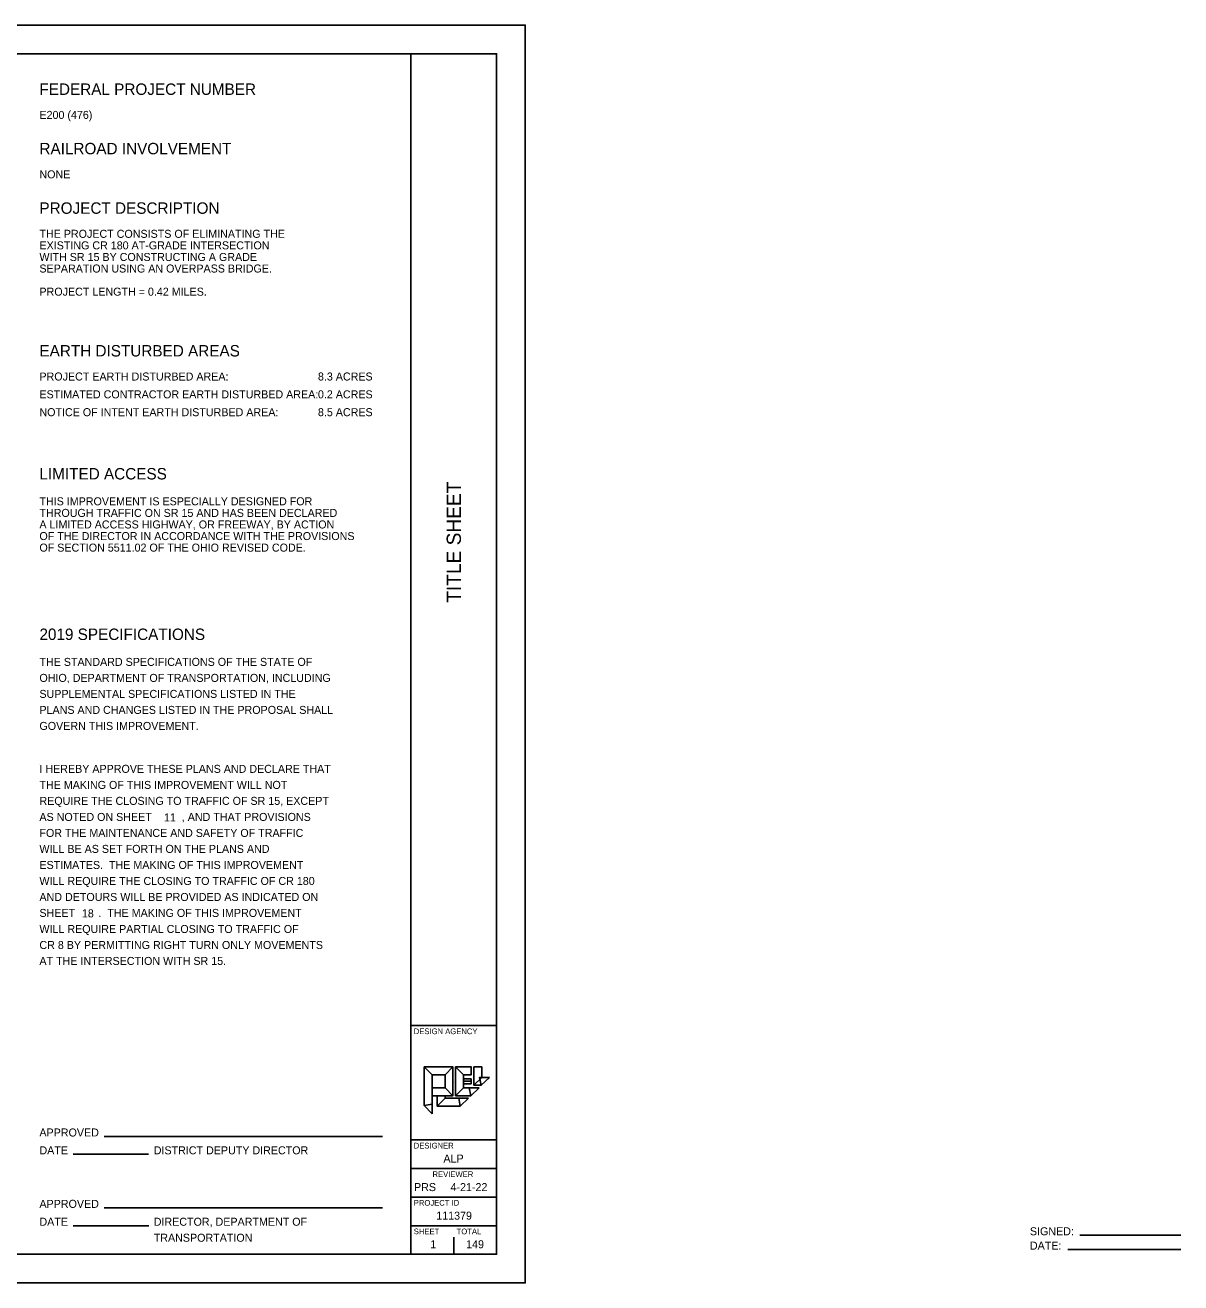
# Model space of a CAD drawing. Extents: x 0 to 45.5, y 0 to 22.
# Drawn here: x 25.25 to 45.47, y 0 to 22 of the extents above; entities that cross this region are included whole.
import ezdxf

# ---------------------------------------------------------------- set-up
doc = ezdxf.new("R2010")
doc.units = 0
for name, color, linetype in [('Default', 7, 'Continuous'), ('SH_Border', 7, 'Continuous'), ('SH_Cut_Line', 7, 'Continuous'), ('SH_Data', 7, 'Continuous')]:
    doc.layers.add(name, color=color, linetype=linetype)

msp = doc.modelspace()

# ---------------------------------------------------------------- linework, layer by layer
at = {"layer": 'Default'}
msp.add_line((32.919, 3.525), (33.056, 3.525), dxfattribs=at)
for points in [[(32.232, 3.1), (32.232, 3.776), (32.37, 3.64), (32.37, 3.128)], [(32.232, 3.776), (32.736, 3.776), (32.599, 3.64), (32.37, 3.64)], [(32.736, 3.776), (32.736, 3.274), (32.599, 3.411), (32.599, 3.64)], [(32.781, 3.274), (32.781, 3.776), (32.919, 3.64), (32.919, 3.411)], [(32.781, 3.776), (33.056, 3.776), (33.056, 3.64), (32.919, 3.64)], [(33.101, 3.456), (33.101, 3.776), (33.239, 3.776), (33.239, 3.594)], [(33.056, 3.566), (33.056, 3.483), (32.92, 3.483), (32.92, 3.566)], [(33.23, 3.456), (33.101, 3.456), (33.239, 3.594), (33.202, 3.594)], [(33.376, 3.594), (33.23, 3.456), (33.202, 3.594)], [(32.736, 3.274), (32.37, 3.274), (32.37, 3.411), (32.599, 3.411)], [(33.047, 3.274), (32.781, 3.274), (32.919, 3.411), (33.019, 3.411)], [(33.192, 3.411), (33.047, 3.274), (33.019, 3.411)], [(32.37, 2.954), (32.232, 3.1), (32.37, 3.128)], [(32.461, 3.091), (32.461, 3.274), (32.599, 3.274), (32.599, 3.228)], [(32.864, 3.091), (32.461, 3.091), (32.599, 3.228), (32.836, 3.228)], [(33.01, 3.228), (32.864, 3.091), (32.836, 3.228)]]:
    msp.add_lwpolyline(points, close=True, dxfattribs=at)
at = {"layer": 'SH_Border'}
for p, q in [((32, 0.5), (32, 21.5)), ((32, 4.5), (33.5, 4.5)), ((32, 2.5), (33.5, 2.5)), ((32, 2), (33.5, 2)), ((32, 1.5), (33.5, 1.5)), ((32, 1), (33.5, 1))]:
    msp.add_line(p, q, dxfattribs=at)
msp.add_lwpolyline([(1.5, 21.5), (33.5, 21.5), (33.5, 0.5), (1.5, 0.5)], close=True, dxfattribs=at)
at = {"layer": 'SH_Cut_Line'}
msp.add_lwpolyline([(0, 0), (34, 0), (34, 22), (0, 22)], close=True, dxfattribs=at)
at = {"layer": 'SH_Data'}
for p, q in [((25.5, 9.06), (25.5, 9.06)), ((32.75, 3.5), (32.75, 3.5)), ((26.635, 2.56), (31.5, 2.56)), ((26.091, 2.248), (27.408, 2.248)), ((26.635, 1.312), (31.5, 1.312)), ((26.091, 0.999), (27.414, 0.999)), ((32.375, 0.675), (32.375, 0.675)), ((32.75, 0.5), (32.75, 0.8)), ((43.701, 0.832), (45.471, 0.832)), ((43.493, 0.581), (45.471, 0.581))]:
    msp.add_line(p, q, dxfattribs=at)

# ---------------------------------------------------------------- texts
at = {"layer": 'Default'}
for s, height, p in [('FEDERAL PROJECT NUMBER', 0.2, (25.5, 20.78)), ('RAILROAD INVOLVEMENT', 0.2, (25.5, 19.741)), ('THIS IMPROVEMENT IS ESPECIALLY DESIGNED FOR', 0.14, (25.5, 13.601)), ('THROUGH TRAFFIC ON SR 15 AND HAS BEEN DECLARED ', 0.14, (25.5, 13.398)), ('A LIMITED ACCESS HIGHWAY, OR FREEWAY, BY ACTION ', 0.14, (25.5, 13.196)), ('OF THE DIRECTOR IN ACCORDANCE WITH THE PROVISIONS ', 0.14, (25.5, 12.993)), ('OF SECTION 5511.02 OF THE OHIO REVISED CODE.', 0.14, (25.5, 12.791)), ('I HEREBY APPROVE THESE PLANS AND DECLARE THAT', 0.14, (25.5, 8.921)), ('THE MAKING OF THIS IMPROVEMENT WILL NOT ', 0.14, (25.5, 8.64)), ('REQUIRE THE CLOSING TO TRAFFIC OF SR 15, EXCEPT', 0.14, (25.5, 8.361)), ('AS NOTED ON SHEET ', 0.14, (25.5, 8.08)), ('11', 0.14, (27.679, 8.071)), (' AND THAT PROVISIONS ', 0.14, (28.043, 8.08)), ('FOR THE MAINTENANCE AND SAFETY OF TRAFFIC ', 0.14, (25.5, 7.8)), (',', 0.14, (27.989, 8.08)), ('WILL BE AS SET FORTH ON THE PLANS AND ', 0.14, (25.5, 7.521)), ('ESTIMATES.  THE MAKING OF THIS IMPROVEMENT', 0.14, (25.5, 7.24)), ('WILL REQUIRE THE CLOSING TO TRAFFIC OF CR 180', 0.14, (25.5, 6.96)), ('AND DETOURS WILL BE PROVIDED AS INDICATED ON', 0.14, (25.5, 6.68)), ('SHEET ', 0.14, (25.5, 6.401)), ('18', 0.14, (26.243, 6.393)), ('.  THE MAKING OF THIS IMPROVEMENT', 0.14, (26.532, 6.401)), ('WILL REQUIRE PARTIAL CLOSING TO TRAFFIC OF', 0.14, (25.5, 6.12)), ('CR 8 BY PERMITTING RIGHT TURN ONLY MOVEMENTS', 0.14, (25.5, 5.84)), ('AT THE INTERSECTION WITH SR 15.', 0.14, (25.5, 5.561)), ('DISTRICT DEPUTY DIRECTOR', 0.14, (27.5, 2.248)), ('DIRECTOR, DEPARTMENT OF', 0.14, (27.5, 0.999)), ('TRANSPORTATION', 0.14, (27.5, 0.719))]:
    msp.add_text(s, height=height, dxfattribs=at).set_placement(p)
at = {"layer": 'SH_Data'}
for s, height, p in [('E200 (476)', 0.14, (25.5, 20.36)), ('NONE', 0.14, (25.5, 19.32)), ('PROJECT DESCRIPTION', 0.2, (25.5, 18.7)), ('THE PROJECT CONSISTS OF ELIMINATING THE', 0.14, (25.5, 18.28)), ('EXISTING CR 180 AT-GRADE INTERSECTION', 0.14, (25.5, 18.078)), ('WITH SR 15 BY CONSTRUCTING A GRADE', 0.14, (25.5, 17.875)), ('SEPARATION USING AN OVERPASS BRIDGE.', 0.14, (25.5, 17.673)), ('PROJECT LENGTH = 0.42 MILES.', 0.14, (25.5, 17.268)), ('EARTH DISTURBED AREAS', 0.2, (25.5, 16.204)), ('PROJECT EARTH DISTURBED AREA:', 0.14, (25.5, 15.784)), ('8.3 ACRES', 0.14, (30.373, 15.784)), ('ESTIMATED CONTRACTOR EARTH DISTURBED AREA:', 0.14, (25.5, 15.472)), ('0.2 ACRES', 0.14, (30.373, 15.472)), ('NOTICE OF INTENT EARTH DISTURBED AREA:', 0.14, (25.5, 15.16)), ('8.5 ACRES', 0.14, (30.373, 15.16)), ('LIMITED ACCESS', 0.2, (25.5, 14.053)), ('2019 SPECIFICATIONS', 0.2, (25.5, 11.245)), ('THE STANDARD SPECIFICATIONS OF THE STATE OF', 0.14, (25.5, 10.792)), ('OHIO, DEPARTMENT OF TRANSPORTATION, INCLUDING', 0.14, (25.5, 10.512)), ('SUPPLEMENTAL SPECIFICATIONS LISTED IN THE', 0.14, (25.5, 10.232)), ('PLANS AND CHANGES LISTED IN THE PROPOSAL SHALL', 0.14, (25.5, 9.952)), ('GOVERN THIS IMPROVEMENT.', 0.14, (25.5, 9.672)), ('DESIGN AGENCY', 0.1, (32.05, 4.35)), ('APPROVED', 0.14, (25.5, 2.56)), ('DESIGNER', 0.1, (32.05, 2.35)), ('DATE', 0.14, (25.5, 2.248)), ('ALP', 0.14, (32.569, 2.105)), ('REVIEWER', 0.1, (32.378, 1.85)), ('PRS', 0.14, (32.054, 1.605)), ('4-21-22', 0.14, (32.693, 1.605)), ('APPROVED', 0.14, (25.5, 1.312)), ('PROJECT ID', 0.1, (32.05, 1.35)), ('DATE', 0.14, (25.5, 0.999)), ('111379', 0.14, (32.443, 1.105)), ('SHEET', 0.1, (32.05, 0.85)), ('TOTAL', 0.1, (32.8, 0.85)), ('SIGNED:', 0.14, (42.83, 0.832)), ('1', 0.14, (32.339, 0.605)), ('149', 0.14, (32.966, 0.605)), ('DATE:', 0.14, (42.83, 0.581))]:
    msp.add_text(s, height=height, dxfattribs=at).set_placement(p)
msp.add_text('TITLE SHEET', height=0.25, rotation=90, dxfattribs=at).set_placement((32.875, 11.897))

doc.saveas('drawing.dxf')
